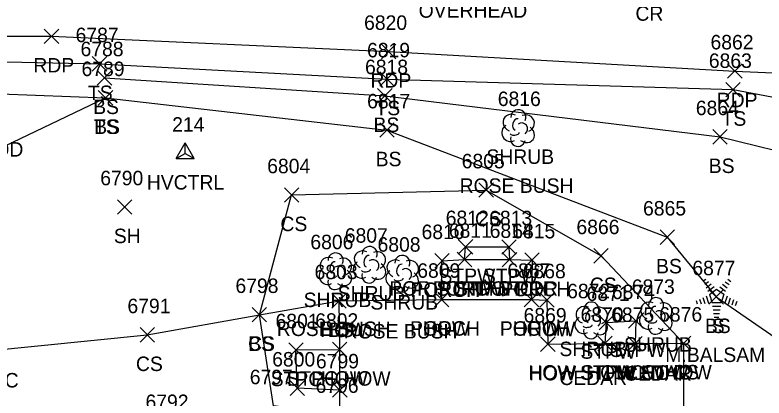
# Model space of a CAD drawing. Extents: x 1443912 to 1445411, y 621446 to 623693.
# Drawn here: x 1444844.8 to 1444948.4, y 622525.2 to 622578.2 of the extents above; entities that cross this region are included whole.
import ezdxf

# ---------------------------------------------------------------- set-up
doc = ezdxf.new("R2010")
doc.units = 0
for name, color, linetype in [('C_A', 7, 'Continuous'), ('C_I', 7, 'Continuous'), ('CPSM', 7, 'Continuous'), ('D_C', 7, 'Continuous'), ('L_A', 7, 'Continuous'), ('L_C', 7, 'Continuous'), ('L_I', 7, 'Continuous'), ('L_TIC', 7, 'Continuous'), ('LBC', 7, 'Continuous'), ('LBF', 7, 'Continuous'), ('LELB', 7, 'Continuous'), ('LSH', 7, 'Continuous'), ('LTC', 7, 'Continuous'), ('P_A', 7, 'Continuous'), ('P_I', 7, 'Continuous'), ('P_TIC', 7, 'Continuous'), ('PET', 7, 'Continuous'), ('U_A', 7, 'Continuous')]:
    doc.layers.add(name, color=color, linetype=linetype)

msp = doc.modelspace()

# ---------------------------------------------------------------- linework, layer by layer
at = {"layer": 'CPSM'}
for p, q in [((1444867.14, 622558.34), (1444868.39, 622560.5)), ((1444869.64, 622558.34), (1444868.39, 622560.5)), ((1444868.39, 622559.06), (1444868.39, 622560.5)), ((1444867.14, 622558.34), (1444868.39, 622559.06)), ((1444868.39, 622559.06), (1444868.39, 622559.06)), ((1444868.39, 622559.06), (1444869.64, 622558.34)), ((1444867.14, 622558.34), (1444869.64, 622558.34))]:
    msp.add_line(p, q, dxfattribs=at)
at = {"layer": 'L_TIC'}
for points in [[(1444855.53, 622570.43), (1444857.53, 622572.43)], [(1444857.53, 622570.43), (1444855.53, 622572.43)], [(1444856.22, 622568.49), (1444858.22, 622570.49)], [(1444858.22, 622568.49), (1444856.22, 622570.49)], [(1444895.29, 622568.33), (1444897.29, 622570.33)], [(1444897.29, 622568.33), (1444895.29, 622570.33)], [(1444895, 622566.01), (1444897, 622568.01)], [(1444897, 622566.01), (1444895, 622568.01)], [(1444943.16, 622566.87), (1444945.16, 622568.87)], [(1444945.16, 622566.87), (1444943.16, 622568.87)], [(1444856.36, 622565.74), (1444858.36, 622567.74)], [(1444858.36, 622565.74), (1444856.36, 622567.74)], [(1444856.36, 622565.74), (1444858.36, 622567.74)], [(1444858.36, 622565.74), (1444856.36, 622567.74)], [(1444895.29, 622561.28), (1444897.29, 622563.28)], [(1444897.29, 622561.28), (1444895.29, 622563.28)], [(1444941.36, 622560.34), (1444943.36, 622562.34)], [(1444943.36, 622560.34), (1444941.36, 622562.34)], [(1444909.01, 622552.99), (1444911.01, 622554.99)], [(1444911.01, 622552.99), (1444909.01, 622554.99)], [(1444882.11, 622552.31), (1444884.11, 622554.31)], [(1444884.11, 622552.31), (1444882.11, 622554.31)], [(1444859.03, 622550.65), (1444861.03, 622552.65)], [(1444861.03, 622550.65), (1444859.03, 622552.65)], [(1444934.07, 622546.47), (1444936.07, 622548.47)], [(1444936.07, 622546.47), (1444934.07, 622548.47)], [(1444906.16, 622545.14), (1444908.16, 622547.14)], [(1444908.16, 622545.14), (1444906.16, 622547.14)], [(1444912.17, 622545.12), (1444914.17, 622547.12)], [(1444914.17, 622545.12), (1444912.17, 622547.12)], [(1444902.9, 622543.21), (1444904.9, 622545.21)], [(1444904.9, 622543.21), (1444902.9, 622545.21)], [(1444906.02, 622543.39), (1444908.02, 622545.39)], [(1444908.02, 622543.39), (1444906.02, 622545.39)], [(1444906.02, 622543.39), (1444908.02, 622545.39)], [(1444908.02, 622543.39), (1444906.02, 622545.39)], [(1444912.24, 622543.37), (1444914.24, 622545.37)], [(1444914.24, 622543.37), (1444912.24, 622545.37)], [(1444912.24, 622543.37), (1444914.24, 622545.37)], [(1444914.24, 622543.37), (1444912.24, 622545.37)], [(1444915.36, 622543.31), (1444917.36, 622545.31)], [(1444917.36, 622543.31), (1444915.36, 622545.31)], [(1444924.9, 622543.89), (1444926.9, 622545.89)], [(1444926.9, 622543.89), (1444924.9, 622545.89)], [(1444940.83, 622538.22), (1444942.83, 622540.22)], [(1444942.83, 622538.22), (1444940.83, 622540.22)], [(1444888.67, 622537.67), (1444890.67, 622539.67)], [(1444890.67, 622537.67), (1444888.67, 622539.67)], [(1444888.67, 622537.67), (1444890.67, 622539.67)], [(1444890.67, 622537.67), (1444888.67, 622539.67)], [(1444902.87, 622537.86), (1444904.87, 622539.86)], [(1444904.87, 622537.86), (1444902.87, 622539.86)], [(1444902.87, 622537.86), (1444904.87, 622539.86)], [(1444904.87, 622537.86), (1444902.87, 622539.86)], [(1444915.29, 622537.85), (1444917.29, 622539.85)], [(1444917.29, 622537.85), (1444915.29, 622539.85)], [(1444915.29, 622537.85), (1444917.29, 622539.85)], [(1444917.29, 622537.85), (1444915.29, 622539.85)], [(1444917.42, 622537.79), (1444919.42, 622539.79)], [(1444919.42, 622537.79), (1444917.42, 622539.79)], [(1444877.65, 622535.76), (1444879.65, 622537.76)], [(1444879.65, 622535.76), (1444877.65, 622537.76)], [(1444877.65, 622535.76), (1444879.65, 622537.76)], [(1444879.65, 622535.76), (1444877.65, 622537.76)], [(1444929.71, 622534.91), (1444931.71, 622536.91)], [(1444931.71, 622534.91), (1444929.71, 622536.91)], [(1444925.64, 622534.67), (1444927.64, 622536.67)], [(1444927.64, 622534.67), (1444925.64, 622536.67)], [(1444862.14, 622532.97), (1444864.14, 622534.97)], [(1444864.14, 622532.97), (1444862.14, 622534.97)], [(1444917.55, 622531.68), (1444919.55, 622533.68)], [(1444919.55, 622531.68), (1444917.55, 622533.68)], [(1444925.46, 622531.78), (1444927.46, 622533.78)], [(1444927.46, 622531.78), (1444925.46, 622533.78)], [(1444925.46, 622531.78), (1444927.46, 622533.78)], [(1444927.46, 622531.78), (1444925.46, 622533.78)], [(1444929.61, 622531.76), (1444931.61, 622533.76)], [(1444931.61, 622531.76), (1444929.61, 622533.76)], [(1444929.61, 622531.76), (1444931.61, 622533.76)], [(1444931.61, 622531.76), (1444929.61, 622533.76)], [(1444936.3, 622531.81), (1444938.3, 622533.81)], [(1444938.3, 622531.81), (1444936.3, 622533.81)], [(1444936.3, 622531.81), (1444938.3, 622533.81)], [(1444938.3, 622531.81), (1444936.3, 622533.81)], [(1444882.7, 622530.88), (1444884.7, 622532.88)], [(1444884.7, 622530.88), (1444882.7, 622532.88)], [(1444888.76, 622530.95), (1444890.76, 622532.95)], [(1444890.76, 622530.95), (1444888.76, 622532.95)], [(1444888.76, 622530.95), (1444890.76, 622532.95)], [(1444890.76, 622530.95), (1444888.76, 622532.95)], [(1444882.89, 622525.6), (1444884.89, 622527.6)], [(1444884.89, 622525.6), (1444882.89, 622527.6)], [(1444888.78, 622525.34), (1444890.78, 622527.34)], [(1444890.78, 622525.34), (1444888.78, 622527.34)], [(1444888.78, 622525.34), (1444890.78, 622527.34)], [(1444890.78, 622525.34), (1444888.78, 622527.34)]]:
    msp.add_lwpolyline(points, dxfattribs=at)
at = {"layer": 'LBC'}
msp.add_lwpolyline([(1444889.66, 622511.63), (1444889.78, 622522.95), (1444889.78, 622526.34), (1444889.76, 622531.95), (1444889.67, 622538.67), (1444903.87, 622538.86), (1444916.29, 622538.85), (1444918.42, 622538.79), (1444918.55, 622532.68), (1444926.46, 622532.78), (1444930.61, 622532.76), (1444937.3, 622532.81), (1444937.34, 622513.34), (1444937.36, 622497.34)], dxfattribs=at)
at = {"layer": 'LBF'}
for points in [[(1444907.02, 622544.39), (1444907.16, 622546.14), (1444913.17, 622546.12), (1444913.24, 622544.37)], [(1444903.87, 622538.86), (1444903.9, 622544.21), (1444907.02, 622544.39), (1444913.24, 622544.37), (1444916.36, 622544.31), (1444916.29, 622538.85)], [(1444926.46, 622532.78), (1444926.64, 622535.67), (1444930.71, 622535.91), (1444930.61, 622532.76)], [(1444889.78, 622526.34), (1444883.89, 622526.6), (1444883.7, 622531.88), (1444889.76, 622531.95)]]:
    msp.add_lwpolyline(points, dxfattribs=at)
at = {"layer": 'LELB'}
for points in [[(1444821.42, 622569.11), (1444832.82, 622571.94), (1444856.53, 622571.43), (1444896.29, 622569.33), (1444944.16, 622567.87), (1444973.57, 622562.32)], [(1444832.82, 622571.94), (1444832.86, 622564.82), (1444835.95, 622556.49), (1444857.36, 622566.74)], [(1444857.22, 622569.49), (1444896, 622567.01), (1444942.36, 622561.34), (1444967.92, 622555.07)], [(1444838.18, 622566.41), (1444837.94, 622567.45), (1444857.36, 622566.74), (1444896.29, 622562.28), (1444935.07, 622547.47), (1444941.83, 622539.22), (1444958.43, 622527.81), (1444968.15, 622516.27), (1444979.47, 622524.13), (1444970.18, 622534.98), (1444967.92, 622555.07)], [(1444840.61, 622531.7), (1444863.14, 622533.97), (1444878.65, 622536.76), (1444883.11, 622553.31), (1444910.01, 622553.99), (1444925.9, 622544.89), (1444937.3, 622532.81)], [(1444889.78, 622522.95), (1444880.62, 622524.15), (1444878.65, 622536.76), (1444889.67, 622538.67)]]:
    msp.add_lwpolyline(points, dxfattribs=at)
at = {"layer": 'LSH'}
for p, q in [((1444914.42, 622562.6), (1444914.42, 622562.6)), ((1444914.42, 622562.6), (1444914.42, 622562.6)), ((1444893.85, 622543.71), (1444893.85, 622543.71)), ((1444893.85, 622543.71), (1444893.85, 622543.71)), ((1444889.14, 622542.81), (1444889.14, 622542.81)), ((1444889.14, 622542.81), (1444889.14, 622542.81)), ((1444898.38, 622542.47), (1444898.38, 622542.47)), ((1444898.38, 622542.47), (1444898.38, 622542.47)), ((1444924.52, 622536.03), (1444924.52, 622536.03)), ((1444924.52, 622536.03), (1444924.52, 622536.03)), ((1444933.46, 622536.64), (1444933.46, 622536.64)), ((1444933.46, 622536.64), (1444933.46, 622536.64))]:
    msp.add_line(p, q, dxfattribs=at)
for centre in [(1444914.46, 622564.04), (1444893.9, 622545.14), (1444889.19, 622544.25), (1444898.42, 622543.91), (1444933.51, 622538.07), (1444924.57, 622537.46)]:
    msp.add_arc(centre, 1.05, 335.5272, 180.9563, dxfattribs=at)
for centre, major_axis, ratio, start_param, end_param in [((1444913.63, 622563.27), (1.21, -0.51), 0.895232, 1.570796, 4.712389), ((1444914.21, 622563.06), (-0.208, -0.792), 0.645439, 3.141593, 6.283185), ((1444915.46, 622563.19), (-1.14, -0.48), 0.949671, 1.570796, 4.712389), ((1444913.33, 622561.89), (0.58, -1.04), 0.959034, 3.141593, 6.283185), ((1444914.92, 622562.44), (-0.5, 0.667), 0.989748, 3.141593, 6.283185), ((1444915.42, 622561.77), (-1.09, 0.79), 0.841452, 1.570796, 4.712389), ((1444913.96, 622561.85), (-0.625, -0.083), 0.423636, 0, 3.141593), ((1444914.42, 622561.1), (0.26, 1.06), 0.942809, 1.570796, 4.712389), ((1444893.06, 622544.37), (1.21, -0.51), 0.895232, 1.570796, 4.712389), ((1444894.89, 622544.29), (-1.14, -0.48), 0.949671, 1.570796, 4.712389), ((1444888.35, 622543.48), (1.21, -0.51), 0.895232, 1.570796, 4.712389), ((1444888.93, 622543.27), (-0.208, -0.792), 0.645439, 3.141593, 6.283185), ((1444890.18, 622543.4), (-1.14, -0.48), 0.949671, 1.570796, 4.712389), ((1444892.77, 622543), (0.58, -1.04), 0.959034, 3.141593, 6.283185), ((1444893.64, 622544.16), (-0.208, -0.792), 0.645439, 3.141593, 6.283185), ((1444894.35, 622543.54), (-0.5, 0.667), 0.989748, 3.141593, 6.283185), ((1444897.58, 622543.14), (1.21, -0.51), 0.895232, 1.570796, 4.712389), ((1444899.42, 622543.06), (-1.14, -0.48), 0.949671, 1.570796, 4.712389), ((1444888.06, 622542.11), (0.58, -1.04), 0.959034, 3.141593, 6.283185), ((1444889.64, 622542.65), (-0.5, 0.667), 0.989748, 3.141593, 6.283185), ((1444893.39, 622542.96), (-0.625, -0.083), 0.423636, 0, 3.141593), ((1444894.85, 622542.87), (-1.09, 0.79), 0.841452, 1.570796, 4.712389), ((1444898.17, 622542.93), (-0.208, -0.792), 0.645439, 3.141593, 6.283185), ((1444898.88, 622542.31), (-0.5, 0.667), 0.989748, 3.141593, 6.283185), ((1444888.68, 622542.06), (-0.625, -0.083), 0.423636, 0, 3.141593), ((1444890.14, 622541.98), (-1.09, 0.79), 0.841452, 1.570796, 4.712389), ((1444893.85, 622542.21), (0.26, 1.06), 0.942809, 1.570796, 4.712389), ((1444897.29, 622541.76), (0.58, -1.04), 0.959034, 3.141593, 6.283185), ((1444899.38, 622541.64), (-1.09, 0.79), 0.841452, 1.570796, 4.712389), ((1444889.14, 622541.31), (0.26, 1.06), 0.942809, 1.570796, 4.712389), ((1444898.38, 622540.97), (0.26, 1.06), 0.942809, 1.570796, 4.712389), ((1444897.92, 622541.72), (-0.625, -0.083), 0.423636, 0, 3.141593), ((1444923.73, 622536.7), (1.21, -0.51), 0.895232, 1.570796, 4.712389), ((1444925.56, 622536.61), (-1.14, -0.48), 0.949671, 1.570796, 4.712389), ((1444932.67, 622537.3), (1.21, -0.51), 0.895232, 1.570796, 4.712389), ((1444933.25, 622537.1), (-0.208, -0.792), 0.645439, 3.141593, 6.283185), ((1444934.5, 622537.22), (-1.14, -0.48), 0.949671, 1.570796, 4.712389), ((1444924.31, 622536.49), (-0.208, -0.792), 0.645439, 3.141593, 6.283185), ((1444925.02, 622535.86), (-0.5, 0.667), 0.989748, 3.141593, 6.283185), ((1444932.38, 622535.93), (0.58, -1.04), 0.959034, 3.141593, 6.283185), ((1444933.96, 622536.47), (-0.5, 0.667), 0.989748, 3.141593, 6.283185), ((1444923.44, 622535.32), (0.58, -1.04), 0.959034, 3.141593, 6.283185), ((1444925.52, 622535.2), (-1.09, 0.79), 0.841452, 1.570796, 4.712389), ((1444933, 622535.89), (-0.625, -0.083), 0.423636, 0, 3.141593), ((1444934.46, 622535.8), (-1.09, 0.79), 0.841452, 1.570796, 4.712389), ((1444924.52, 622534.53), (0.26, 1.06), 0.942809, 1.570796, 4.712389), ((1444924.06, 622535.28), (-0.625, -0.083), 0.423636, 0, 3.141593), ((1444933.46, 622535.14), (0.26, 1.06), 0.942809, 1.570796, 4.712389)]:
    msp.add_ellipse(centre, major_axis=major_axis, ratio=ratio, start_param=start_param, end_param=end_param, dxfattribs=at)
at = {"layer": 'LTC'}
for p, q in [((1444940.03, 622541.43), (1444940.38, 622541.68)), ((1444940.24, 622540.96), (1444940.77, 622541.34)), ((1444940.45, 622540.49), (1444941.15, 622541.01)), ((1444942.68, 622540.97), (1444943.36, 622540.48)), ((1444943.05, 622541.32), (1444943.6, 622540.92)), ((1444943.43, 622541.67), (1444943.85, 622541.36)), ((1444940.66, 622540.03), (1444941.53, 622540.67)), ((1444940.88, 622539.57), (1444941.89, 622540.31)), ((1444941.89, 622540.31), (1444942.89, 622539.58)), ((1444942.31, 622540.62), (1444943.12, 622540.03)), ((1444939.52, 622538.92), (1444939.73, 622538.27)), ((1444939.97, 622539.14), (1444940.24, 622538.3)), ((1444940.43, 622539.35), (1444940.76, 622538.34)), ((1444940.88, 622539.57), (1444941.27, 622538.38)), ((1444942.89, 622539.58), (1444942.5, 622538.38)), ((1444943.33, 622539.31), (1444942.99, 622538.27)), ((1444943.77, 622539.06), (1444943.48, 622538.18)), ((1444939.06, 622538.71), (1444939.21, 622538.24)), ((1444942.5, 622538.38), (1444941.27, 622538.38)), ((1444942.46, 622537.88), (1444941.32, 622537.88)), ((1444944.22, 622538.81), (1444943.98, 622538.08)), ((1444944.66, 622538.56), (1444944.47, 622537.99)), ((1444942.38, 622537.38), (1444941.39, 622537.38)), ((1444942.29, 622536.88), (1444941.46, 622536.88)), ((1444942.21, 622536.38), (1444941.53, 622536.38))]:
    msp.add_line(p, q, dxfattribs=at)
at = {"layer": 'P_TIC'}
for points in [[(1444848.9, 622574.24), (1444850.9, 622576.24)], [(1444850.9, 622574.24), (1444848.9, 622576.24)], [(1444895.52, 622572.13), (1444897.52, 622574.13)], [(1444897.52, 622572.13), (1444895.52, 622574.13)], [(1444943.4, 622569.43), (1444945.4, 622571.43)], [(1444945.4, 622569.43), (1444943.4, 622571.43)]]:
    msp.add_lwpolyline(points, dxfattribs=at)
at = {"layer": 'PET'}
msp.add_lwpolyline([(1444762.32, 622550.87), (1444765.48, 622555.51), (1444771.42, 622562.4), (1444777.98, 622567.72), (1444778.97, 622567.88), (1444793.44, 622574.04), (1444804, 622575.78), (1444819.79, 622575.28), (1444849.9, 622575.24), (1444896.52, 622573.13), (1444944.4, 622570.43), (1444985.66, 622568.62), (1445016.28, 622568.79), (1445055.76, 622567.84), (1445106.1, 622567.18), (1445146.5, 622566.32), (1445185.48, 622566.13), (1445218.5, 622565.93), (1445249.94, 622565.64), (1445288.6, 622564.79), (1445341.53, 622564.99), (1445404.89, 622565.43)], dxfattribs=at)

# ---------------------------------------------------------------- texts
at = {"layer": 'C_A'}
msp.add_text('HVCTRL', height=2, dxfattribs=at).set_placement((1444863.08, 622554.06))
at = {"layer": 'C_I'}
msp.add_text('214', height=2, dxfattribs=at).set_placement((1444866.59, 622562.06))
at = {"layer": 'D_C'}
msp.add_text('18 CGMP-GOOD', height=2, dxfattribs=at).set_placement((1444825.2, 622558.61))
at = {"layer": 'L_A'}
for s, p in [('TS', (1444854.94, 622566.43)), ('BS', (1444855.66, 622564.49)), ('TS', (1444894.7, 622564.33)), ('TS', (1444942.57, 622562.87)), ('TS', (1444855.77, 622561.74)), ('BS', (1444855.8, 622561.74)), ('BS', (1444894.44, 622562.01)), ('SHRUB', (1444910.05, 622557.6)), ('BS', (1444894.73, 622557.28)), ('BS', (1444940.8, 622556.34)), ('CS', (1444881.56, 622548.31)), ('CS', (1444908.46, 622548.99)), ('SH', (1444858.52, 622546.65)), ('BS', (1444933.51, 622542.47)), ('STPW', (1444903.56, 622541.14)), ('STPW', (1444909.56, 622541.12)), ('POR STPW ST', (1444896.61, 622539.39)), ('PORCH', (1444899.53, 622539.21)), ('PORCH', (1444902.64, 622539.39)), ('STPW POR', (1444905.69, 622539.37)), ('PORCH', (1444908.87, 622539.37)), ('PORCH', (1444911.98, 622539.31)), ('CS', (1444924.35, 622539.89)), ('SHRUB', (1444889.48, 622538.71)), ('SHRUB', (1444884.77, 622537.81)), ('SHRUB', (1444894.01, 622537.47)), ('PORCH', (1444899.49, 622533.86)), ('HOW', (1444901.26, 622533.86)), ('PORCH', (1444911.91, 622533.85)), ('HOW', (1444913.67, 622533.85)), ('HOW', (1444915.81, 622533.79)), ('BS', (1444940.27, 622534.22)), ('S', (1444941.22, 622534.22)), ('HOW', (1444887.05, 622533.67)), ('BS', (1444888.11, 622533.67)), ('CS', (1444877.09, 622531.76)), ('BS', (1444877.09, 622531.76)), ('SHRUB', (1444920.15, 622531.03)), ('STPW', (1444923.04, 622530.67)), ('STPW', (1444927.1, 622530.91)), ('SHRUB', (1444929.09, 622531.64)), ('CS', (1444861.58, 622528.97)), ('HOW STPW ST', (1444915.84, 622527.78)), ('HOW', (1444915.94, 622527.68)), ('STPW HOW', (1444922.99, 622527.76)), ('HOW', (1444923.85, 622527.78)), ('HOW', (1444928, 622527.76)), ('HOW', (1444934.68, 622527.81)), ('CS', (1444935.74, 622527.81)), ('WALLC', (1444836.14, 622526.7)), ('STPC', (1444880.21, 622526.88)), ('STPC HOW', (1444882.39, 622526.95)), ('HOW', (1444887.14, 622526.95))]:
    msp.add_text(s, height=2, dxfattribs=at).set_placement(p)
at = {"layer": 'L_C'}
for s, p in [('ROSE BUSH', (1444906.34, 622553.6)), ('ROSE BUSH', (1444881.06, 622533.81)), ('ROSE BUSH', (1444890.3, 622533.47)), ('M.BALSAM', (1444934.79, 622530.22)), ('CEDAR', (1444929.08, 622527.64)), ('CEDAR', (1444920.14, 622527.03))]:
    msp.add_text(s, height=2, dxfattribs=at).set_placement(p)
at = {"layer": 'L_I'}
for s, p in [('6787', (1444853.23, 622574.43)), ('6788', (1444853.91, 622572.49)), ('6819', (1444893.54, 622572.33)), ('6818', (1444893.26, 622570.01)), ('6863', (1444940.81, 622570.87)), ('6789', (1444854.05, 622569.74)), ('6789', (1444854.05, 622569.74)), ('6817', (1444893.55, 622565.28)), ('6816', (1444911.62, 622565.6)), ('6864', (1444939.01, 622564.34)), ('6805', (1444906.63, 622556.99)), ('6804', (1444879.73, 622556.31)), ('6790', (1444856.64, 622554.65)), ('6865', (1444931.71, 622550.47)), ('6812', (1444904.42, 622549.14)), ('6813', (1444910.43, 622549.12)), ('6810', (1444901.08, 622547.21)), ('6811', (1444904.85, 622547.39)), ('6811', (1444904.85, 622547.39)), ('6814', (1444910.5, 622547.37)), ('6814', (1444910.5, 622547.37)), ('6815', (1444913.62, 622547.31)), ('6866', (1444922.5, 622547.89)), ('6807', (1444890.46, 622546.71)), ('6806', (1444885.7, 622545.81)), ('6808', (1444894.99, 622545.47)), ('6877', (1444938.53, 622542.22)), ('6877', (1444938.53, 622542.22)), ('6803', (1444886.28, 622541.67)), ('6803', (1444886.28, 622541.67)), ('6809', (1444900.48, 622541.86)), ('6809', (1444900.48, 622541.86)), ('6867', (1444912.93, 622541.85)), ('6867', (1444912.93, 622541.85)), ('6868', (1444915.07, 622541.79)), ('6798', (1444875.34, 622539.76)), ('6798', (1444875.34, 622539.76)), ('6872', (1444921.21, 622539.03)), ('6874', (1444927.4, 622538.91)), ('6873', (1444930.15, 622539.64)), ('6871', (1444923.9, 622538.67)), ('6791', (1444860.4, 622536.97)), ('6876', (1444933.94, 622535.81)), ('6876', (1444933.94, 622535.81)), ('6801', (1444880.88, 622534.88)), ('6802', (1444886.37, 622534.95)), ('6802', (1444886.37, 622534.95)), ('6869', (1444915.19, 622535.68)), ('6870', (1444923.07, 622535.78)), ('6870', (1444923.07, 622535.78)), ('6875', (1444927.3, 622535.76)), ('6875', (1444927.3, 622535.76)), ('6800', (1444880.42, 622529.6)), ('6799', (1444886.47, 622529.34)), ('6799', (1444886.47, 622529.34)), ('6797', (1444877.32, 622527.15)), ('6796', (1444886.42, 622525.95)), ('6796', (1444886.42, 622525.95)), ('6792', (1444862.9, 622523.72))]:
    msp.add_text(s, height=2, dxfattribs=at).set_placement(p)
at = {"layer": 'LTC'}
msp.add_text('.', height=1.04, rotation=270, dxfattribs=at).set_placement((1444941.78, 622539.32))
at = {"layer": 'P_A'}
for s, p in [('CR', (1444930.66, 622577.39)), ('RDP', (1444847.39, 622570.24)), ('RDP', (1444894.01, 622568.13)), ('RDP', (1444941.89, 622565.43))]:
    msp.add_text(s, height=2, dxfattribs=at).set_placement(p)
at = {"layer": 'P_I'}
for s, p in [('6820', (1444893.13, 622576.13)), ('6862', (1444941.04, 622573.43))]:
    msp.add_text(s, height=2, dxfattribs=at).set_placement(p)
at = {"layer": 'U_A'}
msp.add_text('OVERHEAD', height=2, dxfattribs=at).set_placement((1444900.68, 622577.81))

doc.saveas('drawing.dxf')
